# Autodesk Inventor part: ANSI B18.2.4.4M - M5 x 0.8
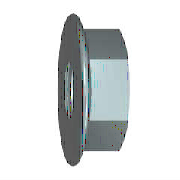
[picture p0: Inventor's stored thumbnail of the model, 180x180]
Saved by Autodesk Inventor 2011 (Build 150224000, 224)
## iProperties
IsCustomPart: 0
Created: 2008-02
Part Number: ANSI B18.2.4.4M - M5 x 0.8
Material: Steel, Mild
Description: Metric Hex Flange Nut
Document SubType Name: Modeling
Standard: ANSI B18.2.4.4M
Designer: PN
Standard Revision: 1999
Standards Organization: ANSI
Language: en-US
Size Designation: M5 x 0.8
Categories: <MemberInstance><Categories><Category DisplayName="Fasteners" InternalName="e4da775c-781d-43d5-af7c-5136215cf5a6" Mnemonic="FSTN"><Category DisplayName="Nuts" I
Density: 7.86 g/cm^3
Mass: 2.42166 g
Surface Area: 3.62968 cm^2
Volume: 0.308099 cm^3
Author: PN
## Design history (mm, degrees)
workaxis "Work Axis1"
workplane "Work Plane1"
revolve "Ring" stored, may be unused: angle "d8" = 90 deg
sketch "Sketch2"
  geometry: L1 (-4, -2.309)-(-4, 2.309); L2 (-4, 2.309)-(0, 4.619); L3 (0, 4.619)-(4, 2.309); L4 (4, 2.309)-(4, -2.309); L5 (4, -2.309)-(0, -4.619); L6 (0, -4.619)-(-4, -2.309); C1 r 4.9 at (0, 0); C2 r 4.9 at (0, 0) reference; 1 further point
  constraints: 12 end point, 1 centre point, 1 coincident, 1 vertical, 11 other
  dimensions: "d6" = 9.2376 distance of L5.end L2.end (= 1.1547 x SW)
extrude "Body" join sketch "Sketch2" distance "d7" = 5 (= KOH); taper "d9" = 0 deg
revolve "Chamfer1" stored, may be unused: angle "d24" = 90 deg
sketch "Sketch4"
  geometry: C1 r 4.9 at (0, 0) reference; 1 further point
  constraints: 1 coincident
hole "Thread" sketch "Sketch4" diameter "d25" = 4.134; stored, may be unused: countersink angle "d29" = 82 deg, drill point angle "d31" = 118 deg; dims "d26" = 6, "d27" = 4, "d28" = 2, "d30" = 8
body "Solid1"
chamfer "Chamfer2" distance "d12" = 0.43301 (= -0.5 x GD1 + 0.5 x NND); stored, may be unused: angle "d13" = 30 deg, second distance "d46" = 0.43301 (= -0.5 x GD1 + 0.5 x NND)
chamfer "Chamfer3" distance "d51" = 0.43301 (= -0.5 x GD1 + 0.5 x NND); stored, may be unused: second distance "d52" = 2, angle "d53" = 45 deg
sketch "Sketch1"
  geometry: L1 (-1.23, 0)-(6.038, 0) reference; L2 (2.674, 4)-(1.866, 5.4); L3 (2.674, 4)-(5, 4); L4 (5, 4)-(5, 0); L5 (2.674, 4)-(2.674, 0); L6 (0, -1.223)-(0, 7.339) reference; A1 r 1 centre (1, 4.9) between (1.866, 5.4) and (0, 4.9); 1 further point
  constraints: 8 end point, 3 point on line, 2 perpendicular, 2 point on circle, 2 tangent, 1 centre point, 1 parallel
  dimensions: "d2" = 8 diameter of L3 L1 (= SW); "d4" = 11.8 dimension on A1 L1 (= LADI); "d5" = 1 radius of A1 (= PHH); "d15" = 5 distance between parallel lines of L4 L6 (= KOH); "d16" = 30 deg angle of L6 L2 (= KEWI)
sketch "Sketch3"
  geometry: L1 (2.317, 4.619)-(5, 4.619) reference; L2 (5, 2.309)-(5, 4.619) reference; L3 (0, -4.9)-(0, 4.9) reference; L4 (-1, 0)-(6, 0) reference; L5 (4.643, 4.619)-(5, 4)
  constraints: 2 end point, 2 point on line
  dimensions: "d10" = 30 deg angle of L2 L5 (= ANG1); "d11" = 8 diameter of L5.end L4 (= SW0)
other parameters: "ANG1" = 30 deg [user parameter; used in 1 equation term], "KEWI" = 30 deg [user parameter; used in 1 equation term], "NND" = 5 [user parameter; used in 3 equation terms], "LADI" = 11.8 [user parameter; used in 2 equation terms], "SW" = 8 [user parameter; used in 4 equation terms], "PHH" = 1 (= RR) [user parameter; used in 2 equation terms], "KOH" = 5 [user parameter; used in 2 equation terms], "SW0" = 8 (= SW) [user parameter; used in 1 equation term], "GD1" = 4.13397 (computed from THREADDIA, PTC, TOA) [user parameter; used in 3 equation terms], "d1" = 11.8 (= LADI), "d3" = 1 (= PHH), "d45" = 0, "d47" = 0, "d49" = 0, "d54" = 0, "GUL" = 0.43301 (= 0.541266 x PTC) [user parameter], "TPU" = 12.5 (computed from PTC) [user parameter], "RR" = 1 [user parameter; used in 1 equation term], "THREADDIA" = 5 [user parameter; used in 1 equation term], "TOA" = 30 deg [user parameter; used in 1 equation term], "PTC" = 0.8 [user parameter; used in 4 equation terms], "RR1" = 0.3 [user parameter], "GAL" = 0.43301 (= 0.541266 x PTC) [user parameter], "E0" = 9.24 (= 1.155 x SW) [user parameter]
